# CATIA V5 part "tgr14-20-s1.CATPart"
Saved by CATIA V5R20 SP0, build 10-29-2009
Part number: TGR14-20-S1
Revision: 1
Definition: design
Nomenclature: TGR14-20-S1
Source: made
Description: NOT SPECIFIED
Bounding box of the stored display mesh (mm): x -22 to 0.8, y 0 to 14, z -7 to 7
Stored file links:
  C:\Users\Raffaele\Desktop\3D X SITO CF\I-MOLD\TGR-S1\tgr14-s1.step\tgr14-20-s1.CATPart
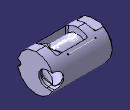
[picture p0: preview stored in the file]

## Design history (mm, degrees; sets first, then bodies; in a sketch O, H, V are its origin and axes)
Set1
  Line1 "LINE #4493": stored without definition
  DatumCurve1 "COMPOSITE_CURVE #4546"
  DatumCurve2 "COMPOSITE_CURVE #4597"
  DatumCurve3 "COMPOSITE_CURVE #4676"
  DatumCurve4 "COMPOSITE_CURVE #4719"
  DatumCurve5 "COMPOSITE_CURVE #4948"
  DatumCurve6 "COMPOSITE_CURVE #5089"
  DatumCurve7 "COMPOSITE_CURVE #5116"
  DatumCurve8 "COMPOSITE_CURVE #5174"
  DatumCurve9 "COMPOSITE_CURVE #5229"
  DatumCurve10 "COMPOSITE_CURVE #5258"
  DatumSurface1 "OPEN_SHELL #4483"
Body1 "MANIFOLD_SOLID_BREP #4484" (main body)
  Solid1: solid without history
